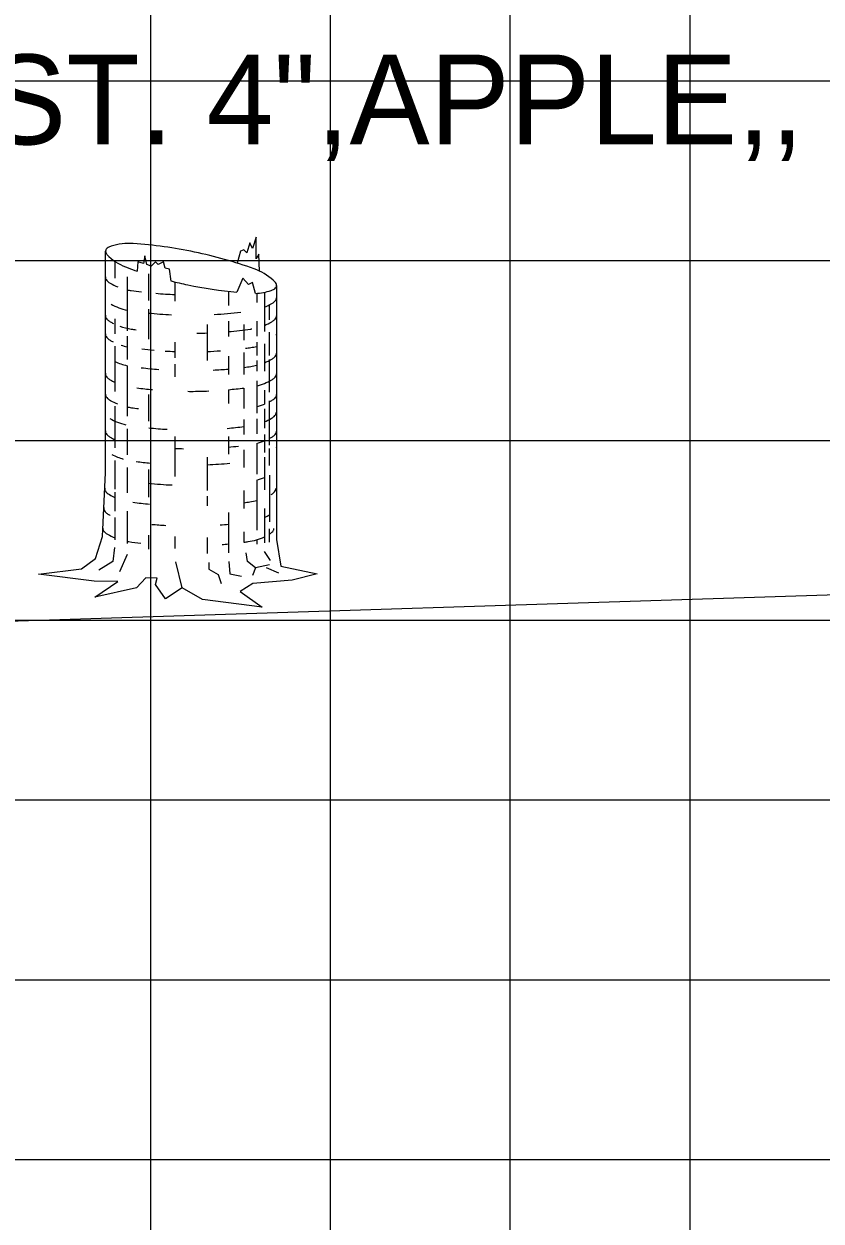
# Model space of a CAD drawing. Extents: x 1147190 to 1147360, y 608981 to 609091.
# Drawn here: x 1147227.24 to 1147231.67, y 609050.99 to 609057.65 of the extents above; entities that cross this region are included whole.
import ezdxf

# ---------------------------------------------------------------- set-up
doc = ezdxf.new("R2010")
doc.units = 0
for name, color, linetype in [('D_Text_Monospaced', 7, 'Continuous'), ('MAJOR', 7, 'Continuous'), ('MINOR', 7, 'Continuous'), ('S_Roadway_Centerline', 7, 'Continuous'), ('S_Trees_Decid_NonPay', 7, 'Continuous')]:
    doc.layers.add(name, color=color, linetype=linetype)

msp = doc.modelspace()

# ---------------------------------------------------------------- linework, layer by layer
at = {"layer": 'MAJOR'}
for p, q in [((1147227.9409, 609045.3351), (1147227.9409, 609065.3351)), ((1147202.9409, 609055.3351), (1147342.9409, 609055.3351))]:
    msp.add_line(p, q, dxfattribs=at)
at = {"layer": 'MINOR'}
for p, q in [((1147228.9409, 609045.3351), (1147228.9409, 609065.3351)), ((1147229.9409, 609045.3351), (1147229.9409, 609065.3351)), ((1147230.9409, 609045.3351), (1147230.9409, 609065.3351)), ((1147202.9409, 609057.3351), (1147342.9409, 609057.3351)), ((1147202.9409, 609056.3351), (1147342.9409, 609056.3351)), ((1147202.9409, 609054.3351), (1147342.9409, 609054.3351)), ((1147202.9409, 609053.3351), (1147342.9409, 609053.3351)), ((1147202.9409, 609052.3351), (1147342.9409, 609052.3351)), ((1147202.9409, 609051.3351), (1147342.9409, 609051.3351))]:
    msp.add_line(p, q, dxfattribs=at)
at = {"layer": 'S_Roadway_Centerline'}
msp.add_lwpolyline([(1147218.6881, 609053.9767), (1147226.4815, 609054.3046), (1147226.7946, 609054.3184), (1147244.6051, 609054.8887), (1147253.4336, 609054.3345), (1147254.6876, 609054.274), (1147257.845, 609055.0498), (1147258.3829, 609055.1775), (1147258.8229, 609055.1791), (1147261.2905, 609055.1012), (1147268.3857, 609055.2101), (1147272.5872, 609055.2789), (1147275.4381, 609055.2118), (1147283.4827, 609055.1294), (1147286.0369, 609055.041), (1147287.2734, 609054.9959), (1147292.8536, 609054.3763), (1147294.8648, 609054.203), (1147300.0193, 609054.043), (1147301.6888, 609053.9626), (1147303.1605, 609054.01), (1147308.9757, 609054.0188), (1147310.1526, 609054.0695), (1147311.9981, 609054.0658)], dxfattribs=at)
at = {"layer": 'S_Trees_Decid_NonPay'}
for p, q in [((1147227.742, 609056.3316), (1147227.742, 609056.2371)), ((1147227.929, 609056.262), (1147227.929, 609056.1137)), ((1147227.8102, 609056.2449), (1147227.8102, 609055.9444)), ((1147228.0759, 609056.2161), (1147228.0759, 609056.1091)), ((1147228.3732, 609056.1636), (1147228.3732, 609056.0848)), ((1147228.5307, 609056.1531), (1147228.5307, 609056.1012)), ((1147228.5733, 609056.1583), (1147228.5733, 609055.9405)), ((1147227.929, 609056.0658), (1147227.929, 609055.8972)), ((1147228.6002, 609056.0881), (1147228.6002, 609056.0061)), ((1147227.742, 609056.0107), (1147227.742, 609055.928)), ((1147228.3732, 609055.9982), (1147228.3732, 609055.9136)), ((1147228.5307, 609055.9982), (1147228.5307, 609055.9156)), ((1147228.2557, 609055.9799), (1147228.2557, 609055.7797)), ((1147228.4598, 609055.9799), (1147228.4598, 609055.8932)), ((1147228.6002, 609055.9365), (1147228.6002, 609055.8066)), ((1147227.742, 609055.8585), (1147227.742, 609055.6072)), ((1147227.8102, 609055.9156), (1147227.8102, 609055.7843)), ((1147228.0759, 609055.8808), (1147228.0759, 609055.7942)), ((1147228.5307, 609055.8808), (1147228.5307, 609055.8066)), ((1147228.5733, 609055.8716), (1147228.5733, 609055.72)), ((1147228.3732, 609055.8027), (1147228.3732, 609055.7016)), ((1147228.4598, 609055.823), (1147228.4598, 609055.7016)), ((1147228.6002, 609055.7843), (1147228.6002, 609055.6026)), ((1147227.8102, 609055.7502), (1147227.8102, 609055.4694)), ((1147228.0759, 609055.7594), (1147228.0759, 609055.6892)), ((1147228.5307, 609055.7797), (1147228.5307, 609055.72)), ((1147228.5307, 609055.6669), (1147228.5307, 609055.4858)), ((1147227.929, 609055.5907), (1147227.929, 609055.4425)), ((1147228.3732, 609055.617), (1147228.3732, 609055.5409)), ((1147228.4598, 609055.6262), (1147228.4598, 609055.512)), ((1147228.5733, 609055.615), (1147228.5733, 609055.5369)), ((1147227.742, 609055.5245), (1147227.742, 609055.2942)), ((1147228.6002, 609055.5553), (1147228.6002, 609055.3086)), ((1147228.4598, 609055.4503), (1147228.4598, 609055.3683)), ((1147228.5307, 609055.4543), (1147228.5307, 609055.3722)), ((1147228.5733, 609055.51), (1147228.5733, 609055.4031)), ((1147227.8102, 609055.3991), (1147227.8102, 609055.2548)), ((1147228.0759, 609055.3558), (1147228.0759, 609055.1334)), ((1147228.3732, 609055.3558), (1147228.3732, 609055.2587)), ((1147228.5307, 609055.3184), (1147228.5307, 609055.1478)), ((1147228.5733, 609055.3683), (1147228.5733, 609055.2673)), ((1147228.4598, 609055.2817), (1147228.4598, 609055.1846)), ((1147228.6002, 609055.2896), (1147228.6002, 609055.1951)), ((1147227.742, 609055.224), (1147227.742, 609055.0632)), ((1147227.8102, 609055.1846), (1147227.8102, 609055.0428)), ((1147228.2557, 609055.2423), (1147228.2557, 609055.0553)), ((1147228.5733, 609055.2417), (1147228.5733, 609055.0593)), ((1147227.929, 609055.1728), (1147227.929, 609055.0199)), ((1147228.6022, 609055.1419), (1147228.6009, 609054.8821)), ((1147228.4598, 609055.0553), (1147228.4598, 609054.9562)), ((1147228.5307, 609055.1144), (1147228.5307, 609054.8348)), ((1147227.742, 609055.0468), (1147227.742, 609054.9418)), ((1147228.2557, 609055.0245), (1147228.2557, 609054.9713)), ((1147227.8102, 609054.9418), (1147227.8102, 609054.7607)), ((1147228.3732, 609054.9339), (1147228.3732, 609054.7095)), ((1147228.5733, 609054.9562), (1147228.5733, 609054.7646)), ((1147227.742, 609054.9051), (1147227.742, 609054.781)), ((1147227.929, 609054.8079), (1147227.929, 609054.7299)), ((1147228.0759, 609054.8001), (1147228.0759, 609054.7338)), ((1147228.2557, 609054.7955), (1147228.2557, 609054.7049)), ((1147228.4598, 609054.827), (1147228.4598, 609054.7686)), ((1147228.6002, 609054.8434), (1147228.6002, 609054.7692)), ((1147228.5307, 609054.7824), (1147228.5307, 609054.7568)), ((1147227.8095, 609054.701), (1147227.7682, 609054.6045)), ((1147228.116, 609054.514), (1147228.0812, 609054.6596)), ((1147228.5714, 609054.7174), (1147228.6061, 609054.6662)), ((1147228.6534, 609054.596), (1147228.5858, 609054.6268))]:
    msp.add_line(p, q, dxfattribs=at)
for points in [[(1147228.5464, 609056.2764), (1147228.5425, 609056.3709), (1147228.528, 609056.344), (1147228.528, 609056.4654), (1147228.507, 609056.4018), (1147228.4926, 609056.4346), (1147228.4762, 609056.3788), (1147228.4598, 609056.3959), (1147228.4414, 609056.3873), (1147228.4224, 609056.3204)], [(1147228.6416, 609056.1957), (1147228.6416, 609054.7837), (1147228.6639, 609054.6354), (1147228.8673, 609054.5921), (1147228.7275, 609054.5566), (1147228.509, 609054.5383), (1147228.4395, 609054.4949), (1147228.5609, 609054.4064), (1147228.2295, 609054.4497), (1147228.116, 609054.514), (1147228.0235, 609054.4536), (1147227.9677, 609054.5324), (1147227.9762, 609054.5691), (1147227.9145, 609054.5711), (1147227.8627, 609054.514), (1147227.6304, 609054.4621), (1147227.7577, 609054.5507), (1147227.6258, 609054.5527), (1147227.3174, 609054.5901), (1147227.5563, 609054.6209), (1147227.6343, 609054.6787), (1147227.6731, 609054.8001), (1147227.6901, 609055.1537), (1147227.6901, 609056.3873)], [(1147228.0543, 609056.2213), (1147228.0458, 609056.2883), (1147228.0215, 609056.2928), (1147228.013, 609056.3276), (1147227.9821, 609056.3132), (1147227.9677, 609056.3276), (1147227.9434, 609056.3047), (1147227.9204, 609056.3132), (1147227.908, 609056.3624), (1147227.9001, 609056.3191), (1147227.8693, 609056.3276), (1147227.866, 609056.2764)], [(1147228.5241, 609056.1524), (1147228.507, 609056.2141), (1147228.4847, 609056.2023), (1147228.4539, 609056.2371), (1147228.4204, 609056.159)], [(1147227.7393, 609054.7384), (1147227.7308, 609054.6616), (1147227.6527, 609054.6124)], [(1147228.2643, 609054.6557), (1147228.2643, 609054.619), (1147228.3154, 609054.5881), (1147228.3325, 609054.5383)], [(1147228.3758, 609054.6616), (1147228.3817, 609054.5921), (1147228.4454, 609054.5796)], [(1147228.5235, 609054.6268), (1147228.4801, 609054.6616), (1147228.4723, 609054.7095)], [(1147228.6022, 609054.6432), (1147228.5235, 609054.6268), (1147228.507, 609054.5835)]]:
    msp.add_lwpolyline(points, dxfattribs=at)
for centre, radius, start, end in [((1147227.7083, 609056.3874), 0.0179, 168.17229, 184.22782), ((1147227.7141, 609056.3878), 0.0237, 184.22782, 198.17229), ((1147227.7083, 609056.3874), 0.0179, 152.11676, 168.17229), ((1147227.7134, 609056.3847), 0.0237, 138.17229, 152.11676), ((1147227.7208, 609056.3781), 0.0336, 119.39599, 138.17229), ((1147227.7502, 609056.3259), 0.0935, 108.17229, 119.39599), ((1147227.8214, 609056.109), 0.3218, 86.05435, 108.17229), ((1147227.6711, 609053.929), 2.507, 78.17229, 86.05435), ((1147227.6711, 609053.929), 2.507, 70.29024, 78.17229), ((1147227.7235, 609056.3909), 0.0336, 198.17229, 216.94859), ((1147227.7714, 609056.4269), 0.0935, 216.9486, 228.17229), ((1147227.9236, 609056.5971), 0.3218, 228.17229, 250.29024), ((1147228.6606, 609058.6542), 2.507, 250.29024, 251.52809), ((1147228.408, 609055.9861), 0.3218, 48.17229, 70.29024), ((1147227.7087, 609056.24), 0.0191, 163.94846, 180), ((1147227.7087, 609056.24), 0.0191, 180, 196.05154), ((1147227.7146, 609056.2417), 0.0252, 196.05154, 210), ((1147227.7237, 609056.2469), 0.0356, 210, 228.74941), ((1147227.7651, 609056.2941), 0.0984, 228.74941, 240), ((1147227.8789, 609056.4913), 0.3261, 240, 248.32432), ((1147228.6606, 609058.6542), 2.507, 255.99867, 258.17229), ((1147228.6606, 609058.6542), 2.507, 258.17229, 264.50134), ((1147228.5603, 609056.1563), 0.0935, 36.9486, 48.17229), ((1147228.6108, 609056.2051), 0.0336, 299.39599, 318.17229), ((1147228.6082, 609056.1923), 0.0336, 18.17229, 36.94859), ((1147228.6182, 609056.1985), 0.0237, 318.17229, 332.11676), ((1147228.6233, 609056.1958), 0.0179, 332.11676, 348.17229), ((1147228.6176, 609056.1954), 0.0237, 4.22782, 18.17229), ((1147228.6233, 609056.1958), 0.0179, 348.17229, 4.22783), ((1147227.8789, 609056.4913), 0.3261, 257.8036, 261.8968), ((1147228.1651, 609058.5013), 2.3564, 261.8968, 263.27991), ((1147228.1651, 609058.5013), 2.3564, 265.24001, 267.83857), ((1147228.5102, 609056.4742), 0.3218, 272.44787, 288.17229), ((1147228.5814, 609056.2573), 0.0935, 288.17229, 299.39599), ((1147228.6155, 609056.1285), 0.0252, 330, 343.94846), ((1147228.6214, 609056.1268), 0.0191, 343.94846, 360), ((1147228.6214, 609056.1268), 0.0191, 360, 6.11276), ((1147227.8789, 609056.3781), 0.3261, 240.90989, 257.8036), ((1147228.4513, 609056.3781), 0.3261, 291.95057, 300), ((1147228.5651, 609056.1809), 0.0984, 300, 311.25059), ((1147228.6065, 609056.1337), 0.0356, 311.25059, 330), ((1147227.7087, 609056.0259), 0.0191, 163.94846, 180), ((1147227.7087, 609056.0259), 0.0191, 180, 196.05154), ((1147227.7146, 609056.0276), 0.0252, 196.05154, 210), ((1147227.7237, 609056.0328), 0.0356, 210, 228.74941), ((1147227.7651, 609056.08), 0.0984, 228.74941, 240), ((1147227.8789, 609056.2772), 0.3261, 240, 243.57187), ((1147228.1651, 609058.3881), 2.3564, 264.24201, 267.36728), ((1147228.1651, 609058.3881), 2.3564, 273.14807, 276.77338), ((1147228.4513, 609056.2772), 0.3261, 291.95057, 300), ((1147228.5651, 609056.08), 0.0984, 300, 311.25059), ((1147228.6065, 609056.0328), 0.0356, 311.25059, 330), ((1147228.6155, 609056.0276), 0.0252, 330, 343.94846), ((1147228.6214, 609056.0259), 0.0191, 343.94846, 360), ((1147228.6214, 609056.0259), 0.0191, 360, 6.11276), ((1147227.7087, 609055.9229), 0.0191, 163.94846, 180), ((1147227.7087, 609055.9229), 0.0191, 180, 196.05154), ((1147227.7146, 609055.9246), 0.0252, 196.05154, 210), ((1147227.8789, 609056.2772), 0.3261, 250.41675, 261.8968), ((1147228.1651, 609058.2872), 2.3564, 261.8968, 262.55191), ((1147228.1651, 609058.2872), 2.3564, 270.81188, 272.1981), ((1147228.1651, 609058.2872), 2.3564, 275.06468, 278.1032), ((1147228.4513, 609056.2772), 0.3261, 278.1032, 279.08543), ((1147228.6214, 609055.9229), 0.0191, 343.94846, 360), ((1147228.6214, 609055.9229), 0.0191, 360, 6.11276), ((1147227.7237, 609055.9298), 0.0356, 210, 228.74941), ((1147227.7651, 609055.977), 0.0984, 228.74941, 240), ((1147227.8789, 609056.1742), 0.3261, 240, 243.24303), ((1147227.8789, 609056.1742), 0.3261, 251.68306, 257.8036), ((1147228.1651, 609058.1842), 2.3564, 277.38384, 278.1032), ((1147228.4513, 609056.1742), 0.3261, 278.1032, 284.03823), ((1147228.1651, 609058.1842), 2.3564, 263.34129, 264.99462), ((1147228.1651, 609058.1842), 2.3564, 266.50356, 267.83857), ((1147228.1651, 609058.1842), 2.3564, 272.1981, 273.97408), ((1147228.4513, 609056.0692), 0.3261, 291.95057, 300), ((1147228.5651, 609055.872), 0.0984, 300, 311.25059), ((1147228.6065, 609055.8248), 0.0356, 311.25059, 330), ((1147228.6155, 609055.8196), 0.0252, 330, 343.94846), ((1147228.6214, 609055.8179), 0.0191, 343.94846, 360), ((1147228.6214, 609055.8179), 0.0191, 360, 6.11276), ((1147227.8789, 609056.0692), 0.3261, 245.15448, 257.8036), ((1147228.1651, 609058.0792), 2.3564, 263.26817, 265.63617), ((1147228.1651, 609058.0792), 2.3564, 273.0067, 275.06467), ((1147228.1651, 609058.0792), 2.3564, 277.18685, 278.1032), ((1147228.4513, 609056.0692), 0.3261, 278.1032, 284.03823), ((1147227.7087, 609055.7029), 0.0191, 163.94846, 180), ((1147227.7087, 609055.7029), 0.0191, 180, 196.05154), ((1147227.7146, 609055.7046), 0.0252, 196.05154, 210), ((1147227.7237, 609055.7098), 0.0356, 210, 228.74941), ((1147227.7651, 609055.757), 0.0984, 228.74941, 240), ((1147227.8789, 609055.9542), 0.3261, 240, 245.15448), ((1147228.4513, 609055.9542), 0.3261, 284.03823, 300), ((1147228.5651, 609055.757), 0.0984, 300, 311.25059), ((1147228.6065, 609055.7098), 0.0356, 311.25059, 330), ((1147228.6155, 609055.7046), 0.0252, 330, 343.94846), ((1147228.6214, 609055.7029), 0.0191, 343.94846, 360), ((1147228.6214, 609055.7029), 0.0191, 360, 6.11276), ((1147227.7095, 609055.5885), 0.0191, 163.94846, 180), ((1147227.7095, 609055.5885), 0.0191, 180, 196.05154), ((1147228.1651, 609057.9642), 2.3564, 262.65877, 264.79114), ((1147228.1651, 609057.9642), 2.3564, 269.55779, 270), ((1147228.1651, 609057.9642), 2.3564, 270, 272.414), ((1147228.1651, 609057.9642), 2.3564, 275.06467, 277.18685), ((1147228.6222, 609055.5885), 0.0191, 343.94846, 360), ((1147228.6222, 609055.5885), 0.0191, 0, 6.11277), ((1147227.7154, 609055.5902), 0.0252, 196.05154, 210), ((1147227.7244, 609055.5954), 0.0356, 210, 228.74941), ((1147227.7658, 609055.6426), 0.0984, 228.74941, 240), ((1147227.8796, 609055.8398), 0.3261, 240, 247.86558), ((1147227.8796, 609055.8398), 0.3261, 257.66994, 261.8968), ((1147228.1658, 609057.8498), 2.3564, 261.8968, 262.86151), ((1147228.452, 609055.8398), 0.3261, 283.90364, 291.80982), ((1147228.452, 609055.8398), 0.3261, 297.00583, 300), ((1147228.5659, 609055.6426), 0.0984, 300, 311.25059), ((1147228.6073, 609055.5954), 0.0356, 311.25059, 330), ((1147228.6163, 609055.5902), 0.0252, 330, 343.94846), ((1147227.7063, 609055.4882), 0.0191, 163.94846, 180), ((1147227.8765, 609055.7395), 0.3261, 240, 256.90786), ((1147228.4489, 609055.7395), 0.3261, 292.40493, 300), ((1147228.5627, 609055.5423), 0.0984, 300, 311.25059), ((1147228.6041, 609055.4951), 0.0356, 311.25059, 330), ((1147228.6131, 609055.4899), 0.0252, 330, 343.94846), ((1147228.6191, 609055.4882), 0.0191, 343.94846, 360), ((1147228.6191, 609055.4882), 0.0191, 0, 6.11277), ((1147227.7087, 609055.3835), 0.0191, 163.94846, 180), ((1147227.7087, 609055.3835), 0.0191, 180, 196.05154), ((1147228.1627, 609057.7495), 2.3564, 264.3443, 266.85288), ((1147228.1627, 609057.7495), 2.3564, 274.97344, 277.24554), ((1147228.6214, 609055.3835), 0.0191, 343.94846, 360), ((1147228.6214, 609055.3835), 0.0191, 360, 6.11276), ((1147227.7146, 609055.3852), 0.0252, 196.05154, 210), ((1147227.7237, 609055.3904), 0.0356, 210, 228.74941), ((1147227.7651, 609055.4376), 0.0984, 228.74941, 240), ((1147227.8789, 609055.6348), 0.3261, 240, 245.15448), ((1147228.4513, 609055.6348), 0.3261, 284.03823, 291.95057), ((1147228.4513, 609055.6348), 0.3261, 297.15252, 300), ((1147228.5651, 609055.4376), 0.0984, 300, 311.25059), ((1147228.6065, 609055.3904), 0.0356, 311.25059, 330), ((1147228.6155, 609055.3852), 0.0252, 330, 343.94846), ((1147227.8789, 609055.5442), 0.3261, 241.93896, 253.9183), ((1147228.1651, 609057.6448), 2.3564, 267.83857, 269.00542), ((1147228.1651, 609057.6448), 2.3564, 275.06467, 276.42799), ((1147228.6214, 609055.2929), 0.0191, 360, 6.11276), ((1147228.1651, 609057.5542), 2.3564, 262.58433, 264.48651), ((1147228.1651, 609057.5542), 2.3564, 272.1981, 275.27259), ((1147228.4513, 609055.4309), 0.3261, 284.03823, 291.95057), ((1147227.7047, 609055.0644), 0.0191, 163.94846, 180), ((1147227.7047, 609055.0644), 0.0191, 180, 196.05154), ((1147227.7106, 609055.0661), 0.0252, 196.05154, 210), ((1147227.7196, 609055.0713), 0.0356, 210, 228.74941), ((1147228.1651, 609057.441), 2.3564, 264.24201, 267.46903), ((1147228.6025, 609055.0713), 0.0356, 311.25059, 330), ((1147228.6115, 609055.0661), 0.0252, 330, 343.94846), ((1147228.6174, 609055.0644), 0.0191, 343.94846, 360), ((1147228.6174, 609055.0644), 0.0191, 360, 6.11276), ((1147227.761, 609055.1185), 0.0984, 228.74941, 240), ((1147227.8748, 609055.3157), 0.3261, 240, 245.93749), ((1147228.161, 609057.3257), 2.3564, 262.22258, 264.4852), ((1147228.161, 609057.3257), 2.3564, 277.28629, 278.1032), ((1147228.4472, 609055.3157), 0.3261, 278.1032, 284.77414), ((1147228.5611, 609055.1185), 0.0984, 300, 311.25059), ((1147227.6998, 609054.9538), 0.0191, 163.94846, 180), ((1147227.6998, 609054.9538), 0.0191, 180, 196.05154), ((1147227.7057, 609054.9555), 0.0252, 196.05154, 210), ((1147227.7147, 609054.9607), 0.0356, 210, 228.74941), ((1147227.7561, 609055.0079), 0.0984, 228.74941, 240), ((1147227.87, 609055.2051), 0.3261, 240, 241.90969), ((1147228.4423, 609055.2051), 0.3261, 293.6544, 300), ((1147228.1561, 609057.2151), 2.3564, 264.90887, 266.81578), ((1147228.1561, 609057.2151), 2.3564, 274.18643, 275.28293), ((1147227.6943, 609054.8435), 0.0191, 163.94846, 180), ((1147227.6943, 609054.8435), 0.0191, 180, 196.05154), ((1147227.7002, 609054.8452), 0.0252, 196.05154, 210), ((1147227.7092, 609054.8505), 0.0356, 210, 228.74941), ((1147227.7506, 609054.8977), 0.0984, 228.74941, 240), ((1147227.8645, 609055.0948), 0.3261, 240, 247.9161), ((1147228.4369, 609055.0948), 0.3261, 278.1032, 294.70938), ((1147228.5507, 609054.8977), 0.0984, 300, 311.25059), ((1147228.5921, 609054.8505), 0.0356, 311.25059, 330), ((1147228.6011, 609054.8452), 0.0252, 330, 343.94846), ((1147228.607, 609054.8435), 0.0191, 343.94846, 360), ((1147228.607, 609054.8435), 0.0191, 0, 6.11277), ((1147227.8645, 609055.0948), 0.3261, 260.38342, 261.8968), ((1147228.1507, 609057.1049), 2.3564, 261.8968, 263.53328), ((1147228.1507, 609057.1049), 2.3564, 274.55512, 275.4167), ((1147228.1507, 609057.1049), 2.3564, 277.54032, 278.1032)]:
    msp.add_arc(centre, radius, start, end, dxfattribs=at)

# ---------------------------------------------------------------- texts
at = {"layer": 'D_Text_Monospaced'}
msp.add_text('EXIST. 4",APPLE,,', height=0.49998, dxfattribs=at).set_placement((1147225.9482, 609056.9814))

doc.saveas('drawing.dxf')
